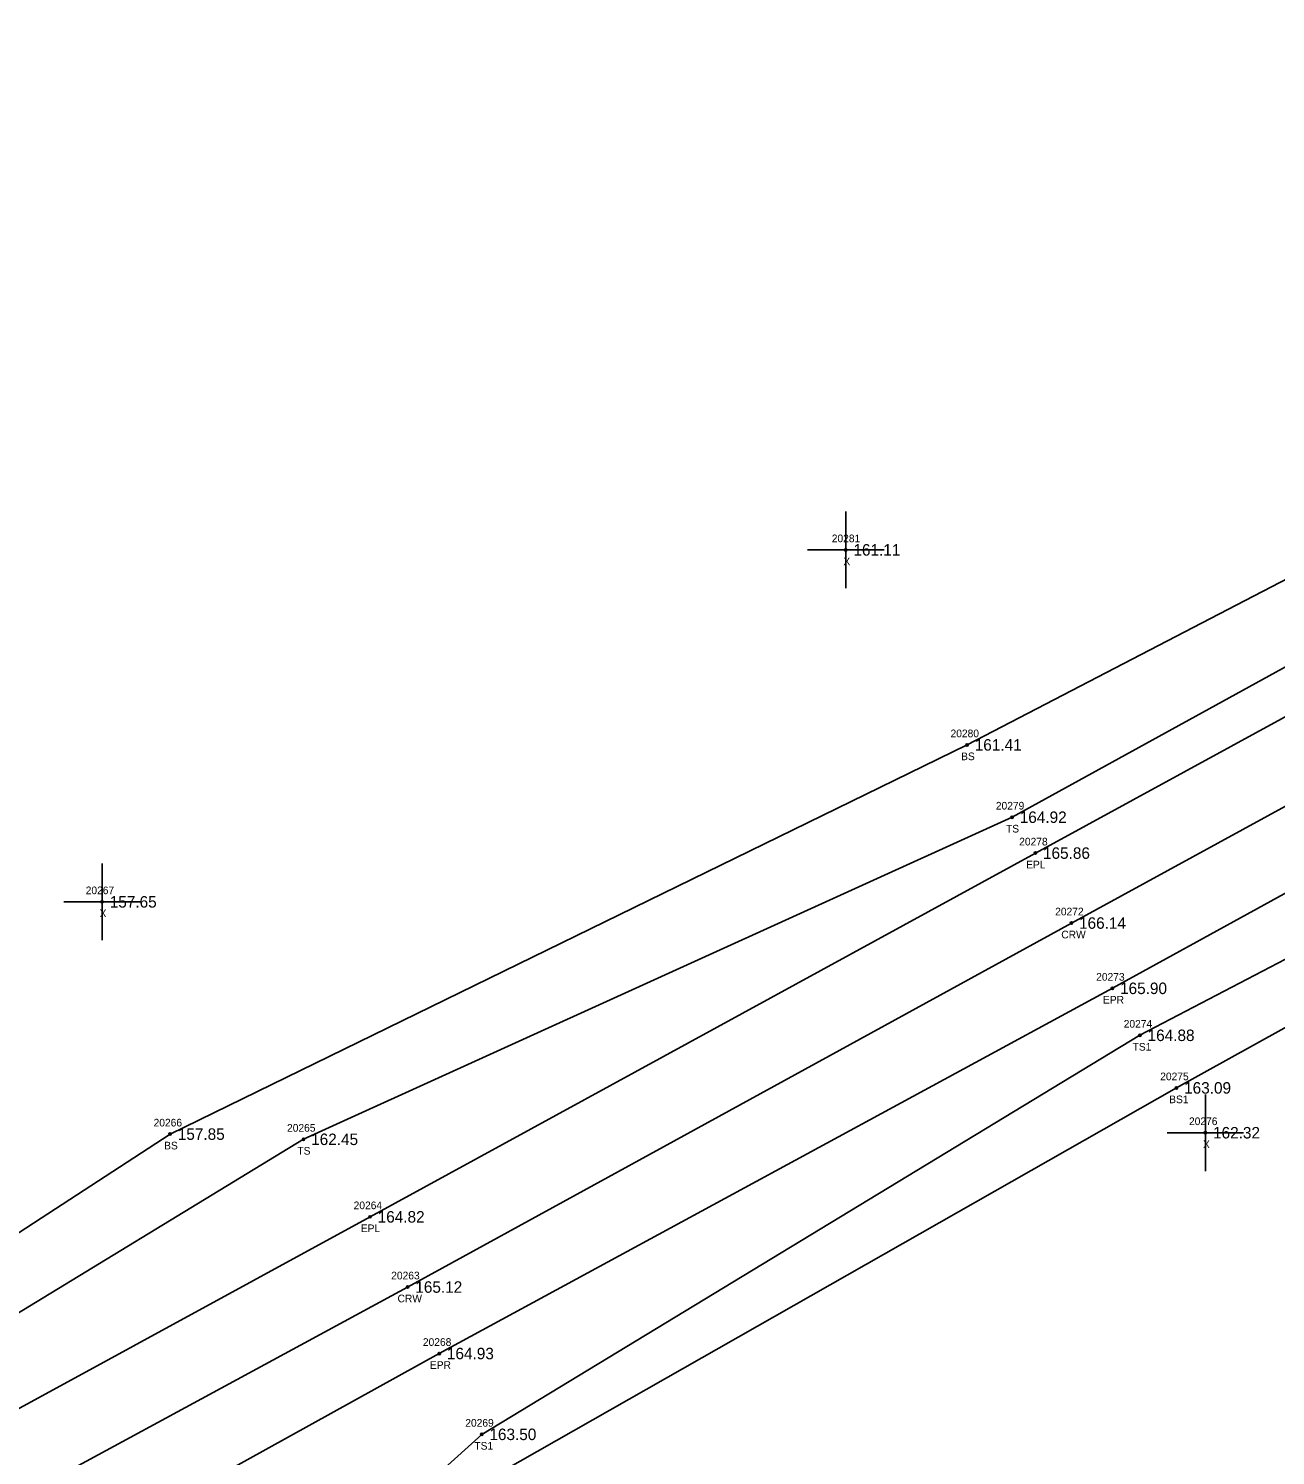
# Model space of a CAD drawing. Extents: x 2279528 to 2280976, y 1061373 to 1062235.
# Drawn here: x 2280261.4 to 2280424.4, y 1061818 to 1062004.5 of the extents above; entities that cross this region are included whole.
import ezdxf

# ---------------------------------------------------------------- set-up
doc = ezdxf.new("R2010")
doc.units = 0
for name, color, linetype in [('RD_DTM_BkLn1', 7, 'Continuous'), ('RD_DTM_BkLn2', 7, 'Continuous'), ('RD_DTM_BkLn_txCode', 7, 'Continuous'), ('RD_EX_Misc', 7, 'Continuous'), ('RD_EX_Misc_txCode', 7, 'Continuous'), ('RD_EX_Road', 7, 'Continuous'), ('RD_EX_Road_txCode', 7, 'Continuous'), ('RD_EX_TX_Misc_ELEV', 7, 'Continuous'), ('RD_EX_TX_Road_ELEV', 7, 'Continuous'), ('RD_HC_Survey_ELEV', 7, 'Continuous'), ('RD_HC_Survey_txCode', 7, 'Continuous'), ('RD_SMD_Locator', 7, 'Continuous')]:
    doc.layers.add(name, color=color, linetype=linetype)

msp = doc.modelspace()

# ---------------------------------------------------------------- linework, layer by layer
at = {"layer": 'RD_DTM_BkLn1'}
msp.add_lwpolyline([(2279559.79, 1061433.13), (2279641.23, 1061477.49), (2279727.93, 1061524.84), (2279814.76, 1061571.75), (2279901.26, 1061618.64), (2279982.8, 1061662.56), (2280064.7, 1061706.86), (2280148.08, 1061751.86), (2280234.22, 1061798.46), (2280310.96, 1061840.01), (2280397.69, 1061887.57), (2280487.27, 1061936.5), (2280573.03, 1061983.12), (2280654.64, 1062027.66), (2280741.28, 1062074.45), (2280833.39, 1062123.87), (2280892.52, 1062155.9), (2280939.46, 1062181.85)], dxfattribs=at)
at = {"layer": 'RD_DTM_BkLn2'}
for points in [[(2280244.17, 1061836.72), (2280279.92, 1061859.99), (2280384.06, 1061910.85), (2280474.95, 1061958.02), (2280563.04, 1062001.93), (2280638.18, 1062044.64), (2280638.45, 1062052), (2280636.3, 1062090.14)], [(2280254.15, 1061833.04), (2280297.35, 1061859.31), (2280389.94, 1061901.4), (2280479.75, 1061950.78), (2280565.23, 1061997.82), (2280647.02, 1062043.23), (2280646.04, 1062059.26), (2280636.3, 1062090.14)], [(2280272.88, 1061795.9), (2280297.58, 1061791.78), (2280309.49, 1061810.68), (2280320.64, 1061820.76), (2280406.65, 1061872.9), (2280496.79, 1061919.98), (2280582.43, 1061964.41), (2280663.95, 1062011.32), (2280685.25, 1062021.45), (2280750.74, 1062056.04), (2280766.13, 1062062.47), (2280799.22, 1062079.83)], [(2280270.02, 1061790.74), (2280279.94, 1061788.98), (2280298.7, 1061789.36), (2280312.74, 1061804.74), (2280323.13, 1061815.81), (2280411.42, 1061866.03), (2280499.93, 1061915.08), (2280584.56, 1061957.49), (2280666.91, 1062006.18), (2280674.46, 1062011.72), (2280685.18, 1062009.25), (2280689.93, 1062011.32), (2280693.25, 1062019.83), (2280753.26, 1062052.49), (2280766.38, 1062057.83), (2280800.29, 1062072.08)]]:
    msp.add_lwpolyline(points, dxfattribs=at)
at = {"layer": 'RD_EX_Misc'}
for p, q in [((2280368.21, 1061931.33), (2280368.21, 1061941.33)), ((2280363.21, 1061936.33), (2280373.21, 1061936.33)), ((2280271.03, 1061885.34), (2280271.03, 1061895.34)), ((2280266.03, 1061890.34), (2280276.03, 1061890.34)), ((2280415.2, 1061855.17), (2280415.2, 1061865.17)), ((2280410.2, 1061860.17), (2280420.2, 1061860.17))]:
    msp.add_line(p, q, dxfattribs=at)
at = {"layer": 'RD_EX_Road'}
for points in [[(2279554.31, 1061441.46), (2279636.61, 1061486.51), (2279673.46, 1061506.76), (2279683.06, 1061512.21), (2279723.14, 1061533.54), (2279809.28, 1061580.29), (2279896.91, 1061627.91), (2279977.07, 1061671.02), (2280059.64, 1061715.57), (2280142.91, 1061760.72), (2280228.83, 1061807.06), (2280306.04, 1061849.18), (2280392.98, 1061896.71), (2280482.82, 1061945.75), (2280567.83, 1061991.78), (2280649.94, 1062036.55), (2280660.56, 1062042.19), (2280676.12, 1062050.66), (2280737.28, 1062083.64), (2280828.54, 1062132.77), (2280887.86, 1062164.61), (2280934.91, 1062190.9)], [(2279906, 1061609.76), (2279987.33, 1061653.65), (2280069.09, 1061697.76), (2280153.19, 1061743.35), (2280194.51, 1061765.35), (2280202.82, 1061771.34), (2280211.47, 1061775.32), (2280215.93, 1061780.7), (2280225.22, 1061785.77), (2280231.78, 1061787.38), (2280251.88, 1061797.82), (2280255.66, 1061801.36), (2280256.83, 1061804.75), (2280266.2, 1061806.83), (2280270.78, 1061807.29), (2280284.33, 1061814.31), (2280315.09, 1061831.32), (2280403.05, 1061879.04), (2280492, 1061927.92)]]:
    msp.add_lwpolyline(points, dxfattribs=at)
at = {"layer": 'RD_SMD_Locator'}
for centre in [(2280368.21, 1061936.33), (2280384.06, 1061910.85), (2280389.94, 1061901.4), (2280392.98, 1061896.71), (2280271.03, 1061890.34), (2280397.69, 1061887.57), (2280403.05, 1061879.04), (2280406.65, 1061872.9), (2280411.42, 1061866.03), (2280279.92, 1061859.99), (2280415.2, 1061860.17), (2280297.35, 1061859.31), (2280306.04, 1061849.18), (2280310.96, 1061840.01), (2280315.09, 1061831.32), (2280320.64, 1061820.76)]:
    msp.add_circle(centre, 0.15, dxfattribs=at)

# ---------------------------------------------------------------- texts
at = {"layer": 'RD_DTM_BkLn_txCode'}
for s, p in [('20280', (2280381.9, 1061911.85)), ('BS', (2280383.28, 1061908.85)), ('20279', (2280387.82, 1061902.4)), ('TS', (2280389.14, 1061899.4)), ('20274', (2280404.53, 1061873.9)), ('TS1', (2280405.69, 1061870.9)), ('20275', (2280409.3, 1061867.03)), ('BS1', (2280410.47, 1061864.03)), ('20266', (2280277.76, 1061860.99)), ('20265', (2280295.2, 1061860.31)), ('BS', (2280279.14, 1061857.99)), ('TS', (2280296.55, 1061857.31)), ('20269', (2280318.49, 1061821.76)), ('TS1', (2280319.68, 1061818.76))]:
    msp.add_text(s, height=1, dxfattribs=at).set_placement(p)
at = {"layer": 'RD_EX_Misc_txCode'}
for s, p in [('20281', (2280366.38, 1061937.33)), ('X', (2280367.9, 1061934.33)), ('20267', (2280268.89, 1061891.34)), ('X', (2280270.71, 1061888.34)), ('20276', (2280413.06, 1061861.17)), ('X', (2280414.89, 1061858.17))]:
    msp.add_text(s, height=1, dxfattribs=at).set_placement(p)
at = {"layer": 'RD_EX_Road_txCode'}
for s, p in [('20278', (2280390.87, 1061897.71)), ('EPL', (2280391.78, 1061894.71)), ('20273', (2280400.93, 1061880.04)), ('EPR', (2280401.82, 1061877.04)), ('20264', (2280303.9, 1061850.18)), ('EPL', (2280304.84, 1061847.18)), ('20268', (2280312.95, 1061832.32)), ('EPR', (2280313.87, 1061829.32))]:
    msp.add_text(s, height=1, dxfattribs=at).set_placement(p)
at = {"layer": 'RD_EX_TX_Misc_ELEV'}
for s, p in [('161.11', (2280369.21, 1061935.58)), ('161.41', (2280385.06, 1061910.1)), ('164.92', (2280390.94, 1061900.65)), ('157.65', (2280272.03, 1061889.59)), ('164.88', (2280407.65, 1061872.15)), ('163.09', (2280412.42, 1061865.28)), ('157.85', (2280280.92, 1061859.24)), ('162.45', (2280298.35, 1061858.56)), ('162.32', (2280416.2, 1061859.42)), ('163.50', (2280321.64, 1061820.01))]:
    msp.add_text(s, height=1.5, dxfattribs=at).set_placement(p)
at = {"layer": 'RD_EX_TX_Road_ELEV'}
for s, p in [('165.86', (2280393.98, 1061895.96)), ('165.90', (2280404.05, 1061878.29)), ('164.82', (2280307.04, 1061848.43)), ('164.93', (2280316.09, 1061830.57))]:
    msp.add_text(s, height=1.5, dxfattribs=at).set_placement(p)
at = {"layer": 'RD_HC_Survey_ELEV'}
for s, p in [('166.14', (2280398.69, 1061886.82)), ('165.12', (2280311.96, 1061839.26))]:
    msp.add_text(s, height=1.5, dxfattribs=at).set_placement(p)
at = {"layer": 'RD_HC_Survey_txCode'}
for s, p in [('20272', (2280395.57, 1061888.57)), ('CRW', (2280396.37, 1061885.57)), ('20263', (2280308.81, 1061841.01)), ('CRW', (2280309.64, 1061838.01))]:
    msp.add_text(s, height=1, dxfattribs=at).set_placement(p)

doc.saveas('drawing.dxf')
